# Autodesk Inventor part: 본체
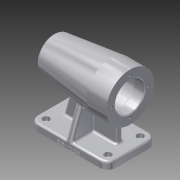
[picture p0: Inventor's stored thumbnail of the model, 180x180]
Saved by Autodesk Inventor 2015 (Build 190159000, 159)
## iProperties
Created: 2018-09
Part Number: 본체
Material: 알루미늄 6061
Document SubType Name: Modeling
Designer: line
Density: 2.7 g/cm^3
Appearance: 알루미늄 - 평지
Mass: 733.229 g
Surface Area: 665.024 cm^2
Volume: 271.566 cm^3
Author: line
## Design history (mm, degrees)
sketch "스케치1"
  geometry: L1 (-56, 35)-(56, 35); L2 (56, 35)-(56, -35); L3 (56, -35)-(-56, -35); L4 (-56, -35)-(-56, 35); 3 further points
  constraints: 8 end point, 2 midpoint, 2 parallel, 1 horizontal, 1 horizontal alignment, 1 perpendicular, 1 vertical alignment
  dimensions: "d0" = 112 distance of L1.start L1.end; "d1" = 70 distance of L3.end L1.start
extrude "돌출1" new body sketch "스케치1" distance "d2" = 10; taper "d3" = 0 deg
sketch "스케치2"
  geometry: L1 (-112.029, 74)-(112.029, 74); L2 (-56, 0)-(56, 0) reference; L3 (52.707, 108)-(24.707, 108); L4 (24.707, 108)-(-55.567, 98.144); L5 (24.707, 108)-(-97.199, 108); L6 (52.707, 108)-(52.707, 95); L7 (52.707, 95)-(37.707, 95); L8 (37.707, 95)-(37.707, 98); L9 (37.707, 98)-(-16.293, 98); L10 (-16.293, 98)-(-16.293, 95); L11 (-16.293, 95)-(-28.293, 95); L12 (-28.293, 95)-(-28.293, 91.5); L13 (-28.293, 91.5)-(-46.293, 91.5); L14 (-46.293, 91.5)-(-46.293, 90); L15 (-46.293, 90)-(-50.293, 90); L16 (-50.293, 90)-(-50.293, 84.5); L17 (-50.293, 84.5)-(-53.293, 84.5); L18 (-53.293, 84.5)-(-53.293, 74); L19 (-59.293, 74)-(-53.293, 74); A1 r 80.087 centre (20.795, 74) between (-55.567, 98.144) and (-59.293, 74); 2 further points
  constraints: 36 end point, 9 perpendicular, 5 point on line, 3 horizontal, 2 point on circle, 2 vertical, 1 centre point, 1 collinear, 1 midpoint, 1 parallel, 1 vertical alignment
  dimensions: "d4" = 74 distance between parallel lines of L2 L1; "d5" = 28 distance of L3.start L3.end; "d8" = 7 deg angle of L4 L5; "d9" = 15 distance of L6.end L7.end; "d11" = 54 distance of L8.end L9.end; "d12" = 12 distance of L10.end L11.end; "d13" = 18 distance of L12.end L13.end; "d14" = 4 distance of L14.end L15.end; "d15" = 3 distance of L16.end L17.end; "d16" = 34 distance between parallel lines of L1 L3; "d17" = 21 distance between parallel lines of L1 L7; "d18" = 24 distance between parallel lines of L1 L9; "d19" = 10.5 distance between parallel lines of L1 L17; "d20" = 16 distance between parallel lines of L1 L15; "d21" = 17.5 distance between parallel lines of L1 L13
revolve "회전1" sketch "스케치2" stored, may be unused: angle "d22" = 90 deg
sketch "스케치5"
  geometry: L1 (56, 10)-(38, 10); L2 (-56, 10)-(56, 10) reference; L3 (38, 10)-(38, 42.927); L4 (-56, 10)-(-38, 10); L5 (-38, 10)-(-27.226, 50.208); L6 (38, 42.927)-(-27.226, 50.208); L7 (38, 10)-(-38.076, 10); 1 further point
  constraints: 12 end point, 3 point on line, 1 perpendicular
  dimensions: "d30" = 18 distance of L1.start L1.end; "d31" = 18 distance of L2.start L4.end; "d32" = 105 deg angle of L2 L5
extrude "돌출3" join sketch "스케치5" stored distance "d33" = 8; taper "d34" = 0 deg
sketch "스케치6"
  geometry: L1 (35, 10)-(22.338, 44.79); L2 (35, 10)-(35, 39.024); 1 further point
  constraints: 4 end point, 1 vertical
  dimensions: "d35" = 20 deg angle of L1 L2
feature "리브1" sketch "스케치6" dims "d36" = 1, "d37" = 8, "d38" = 0, "d39" = 0, "d40" = 1, "d41" = 1
sketch "스케치7"
  geometry: 1 further point
fillet "모깎기1" dims "d42" = 12
hole "구멍1" diameter "d45" = 5.5; stored, may be unused: countersink angle "d49" = 90 deg, drill point angle "d51" = 118 deg; dims "d43" = 10, "d44" = 10, "d46" = 6, "d47" = 9.5, "d48" = 5.4, "d50" = 10
sketch "스케치8" dims "d58" = 26
  geometry: 3 further points
  constraints: 1 horizontal alignment, 2 other
hole "구멍2" sketch "스케치8" at (26, 0) diameter "d59" = 3.242; stored, may be unused: countersink angle "d63" = 90 deg, drill point angle "d65" = 118 deg; dims "d60" = 8, "d61" = 9.5, "d62" = 5.4, "d64" = 11
fillet "모깎기2" dims "d69" = 3
sketch "스케치9"
  geometry: 1 further point
fillet "모깎기3" dims "d70" = 3, "d71" = 0.3
fillet "모깎기4" dims "d72" = 3
chamfer "모따기1" distance "d73" = 1; stored, may be unused: second distance "d74" = 2, angle "d75" = 45 deg
sketch "스케치10"
  geometry: L1 (0, 0)-(88, 0) reference; L2 (-12, 0)-(-12, -7) reference; 2 further points
  constraints: 1 other
  dimensions: "d76" = 3 distance from line of L1 point (44, -3); "d77" = 56 distance from line of L2 point (44, -3)
feature "엠보싱1" sketch "스케치10" dims "d0" = 112, "d1" = 70, "d4" = 74, "d5" = 28, "d8" = 7 deg, "d9" = 15, "d11" = 54, "d12" = 12, "d13" = 18, "d14" = 4, "d15" = 3, "d16" = 34, "d17" = 21, "d18" = 24, "d19" = 10.5, "d20" = 16, "d21" = 17.5, "d78" = 0.5, "d79" = 0
fillet "모깎기5" dims "d80" = 3
fillet "모깎기6" dims "d81" = 3
fillet "모깎기7" dims "d82" = 3
node "솔리드1"
mirror "대칭1"
pattern_linear "직사각형 패턴1" dims "d54" = 46, "d57" = 88
pattern_circular "원형 패턴1" dims angle "d67" = 360 deg
other parameters: "d10" = 112, "d25" = 8, "d26" = 8
